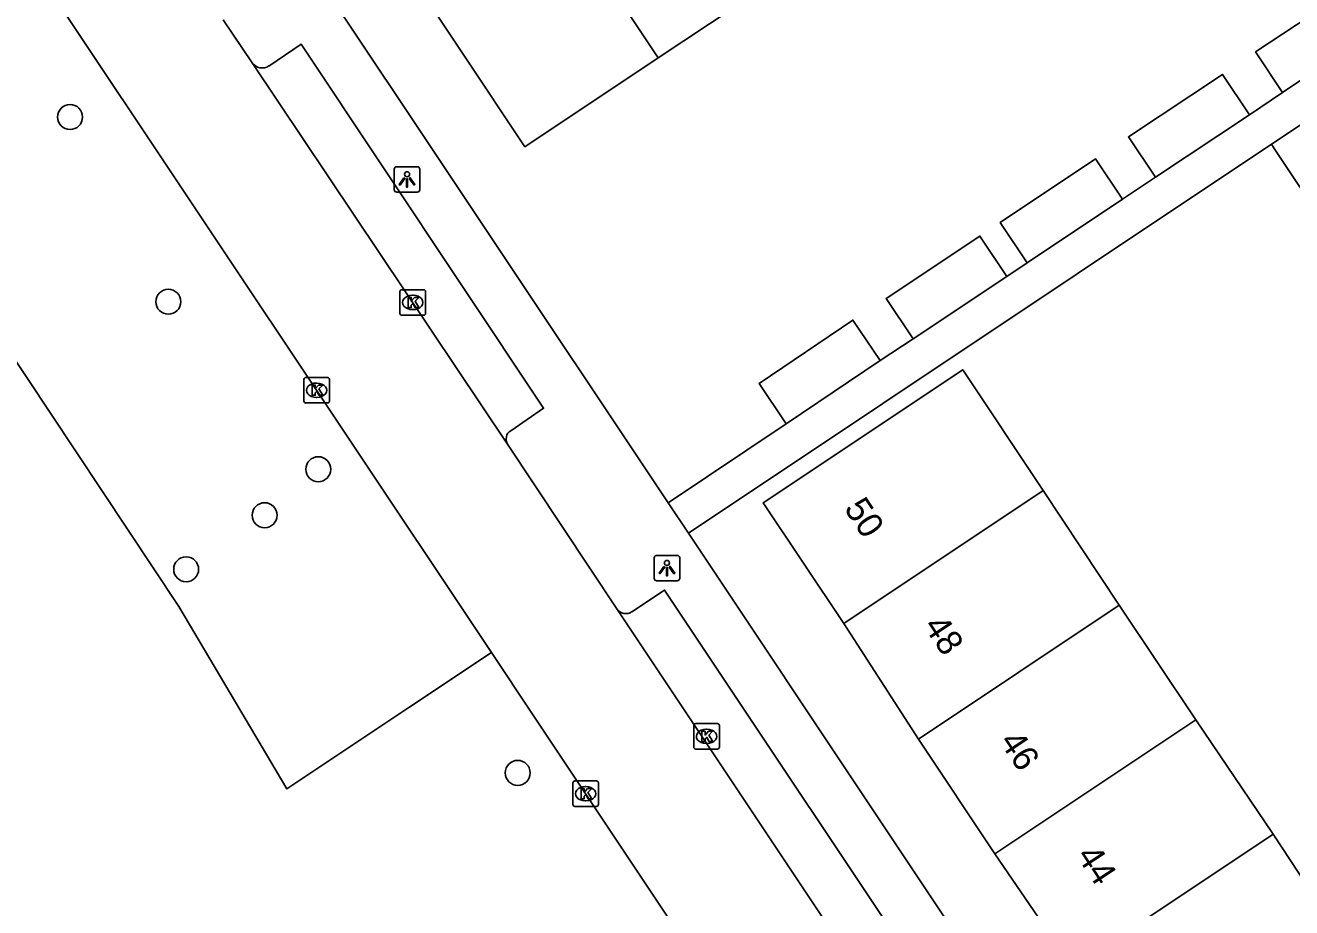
# Model space of a CAD drawing. Extents: x 158352 to 159489, y 383828 to 384597.
# Drawn here: x 158635.92 to 158685.53, y 384292.05 to 384326.59 of the extents above; entities that cross this region are included whole.
import ezdxf

# ---------------------------------------------------------------- set-up
doc = ezdxf.new("R2010")
doc.units = 0
for name, color, linetype in [('IMGEO_Boom', 7, 'Continuous'), ('IMGEO_Groenvoorziening', 7, 'Continuous'), ('IMGEO_Kolk', 7, 'Continuous'), ('IMGEO_Lichtpunt', 7, 'Continuous'), ('IMGEO_Pand', 7, 'Continuous'), ('IMGEO_Pand_nummerreeks', 7, 'Continuous'), ('IMGEO_Rijbaan_lokaal_open', 7, 'Continuous'), ('IMGEO_Voetpad_open', 7, 'Continuous')]:
    doc.layers.add(name, color=color, linetype=linetype)

msp = doc.modelspace()

# ---------------------------------------------------------------- linework, layer by layer
at = {"layer": 'IMGEO_Boom'}
for centre in [(158637.667, 384322.998), (158641.518, 384315.767), (158647.39, 384309.211), (158645.288, 384307.409), (158642.216, 384305.295), (158655.205, 384297.324)]:
    msp.add_circle(centre, 0.489, dxfattribs=at)
at = {"layer": 'IMGEO_Groenvoorziening'}
msp.add_lwpolyline([(158636.795, 384328.082), (158633.416, 384326.021), (158630.193, 384330.83), (158625.907, 384327.948), (158641.933, 384303.831), (158646.165, 384296.695), (158646.519, 384296.93), (158650.939, 384299.878), (158654.177, 384302.038)], dxfattribs=at)
at = {"layer": 'IMGEO_Kolk'}
for p, q in [((158650.592, 384315.312), (158650.592, 384316.164)), ((158650.667, 384316.238), (158651.519, 384316.238)), ((158651.08, 384316.018), (158651.105, 384316.018)), ((158651.593, 384316.164), (158651.593, 384315.312)), ((158651.103, 384315.458), (158651.078, 384315.458)), ((158651.519, 384315.238), (158650.667, 384315.238)), ((158646.827, 384311.877), (158646.827, 384312.729)), ((158646.902, 384312.803), (158647.754, 384312.803)), ((158647.315, 384312.583), (158647.34, 384312.583)), ((158647.828, 384312.729), (158647.828, 384311.877)), ((158647.338, 384312.023), (158647.313, 384312.023)), ((158647.754, 384311.803), (158646.902, 384311.803)), ((158662.103, 384298.329), (158662.103, 384299.181)), ((158662.178, 384299.255), (158663.03, 384299.255)), ((158662.591, 384299.035), (158662.616, 384299.035)), ((158663.104, 384299.181), (158663.104, 384298.329)), ((158662.614, 384298.475), (158662.589, 384298.475)), ((158663.03, 384298.255), (158662.178, 384298.255)), ((158657.441, 384297.008), (158658.293, 384297.008)), ((158657.366, 384296.082), (158657.366, 384296.934)), ((158657.854, 384296.788), (158657.879, 384296.788)), ((158658.367, 384296.934), (158658.367, 384296.082)), ((158658.293, 384296.008), (158657.441, 384296.008)), ((158657.877, 384296.228), (158657.852, 384296.228))]:
    msp.add_line(p, q, dxfattribs=at)
for points in [[(158650.592, 384315.312), (158650.592, 384316.164)], [(158650.667, 384316.238), (158651.519, 384316.238)], [(158650.913, 384315.938), (158651.036, 384315.938), (158651.036, 384315.787), (158651.166, 384315.938), (158651.33, 384315.938), (158651.184, 384315.787), (158651.337, 384315.538), (158651.185, 384315.538), (158651.1, 384315.702), (158651.036, 384315.635), (158651.036, 384315.538), (158650.913, 384315.538), (158650.913, 384315.938)], [(158651.593, 384316.164), (158651.593, 384315.312)], [(158651.519, 384315.238), (158650.667, 384315.238)], [(158646.827, 384311.877), (158646.827, 384312.729)], [(158646.902, 384312.803), (158647.754, 384312.803)], [(158647.148, 384312.503), (158647.271, 384312.503), (158647.271, 384312.352), (158647.401, 384312.503), (158647.565, 384312.503), (158647.419, 384312.352), (158647.572, 384312.103), (158647.42, 384312.103), (158647.335, 384312.267), (158647.271, 384312.2), (158647.271, 384312.103), (158647.148, 384312.103), (158647.148, 384312.503)], [(158647.828, 384312.729), (158647.828, 384311.877)], [(158647.754, 384311.803), (158646.902, 384311.803)], [(158662.103, 384298.329), (158662.103, 384299.181)], [(158662.178, 384299.255), (158663.03, 384299.255)], [(158662.424, 384298.955), (158662.547, 384298.955), (158662.547, 384298.804), (158662.677, 384298.955), (158662.841, 384298.955), (158662.695, 384298.804), (158662.848, 384298.555), (158662.696, 384298.555), (158662.611, 384298.719), (158662.547, 384298.652), (158662.547, 384298.555), (158662.424, 384298.555), (158662.424, 384298.955)], [(158663.104, 384299.181), (158663.104, 384298.329)], [(158663.03, 384298.255), (158662.178, 384298.255)], [(158657.441, 384297.008), (158658.293, 384297.008)], [(158657.366, 384296.082), (158657.366, 384296.934)], [(158657.687, 384296.708), (158657.81, 384296.708), (158657.81, 384296.557), (158657.94, 384296.708), (158658.104, 384296.708), (158657.958, 384296.557), (158658.111, 384296.308), (158657.959, 384296.308), (158657.874, 384296.472), (158657.81, 384296.405), (158657.81, 384296.308), (158657.687, 384296.308), (158657.687, 384296.708)], [(158658.367, 384296.934), (158658.367, 384296.082)], [(158658.293, 384296.008), (158657.441, 384296.008)]]:
    msp.add_lwpolyline(points, dxfattribs=at)
for centre, start, end in [((158650.669, 384316.162), 91.552, 178.448), ((158650.669, 384316.162), 91.552, 178.448), ((158651.517, 384316.162), 1.552, 88.448), ((158651.517, 384316.162), 1.552, 88.448), ((158650.669, 384315.314), 181.552, 268.448), ((158650.669, 384315.314), 181.552, 268.448), ((158651.517, 384315.314), 271.552, 358.448), ((158651.517, 384315.314), 271.552, 358.448), ((158646.904, 384312.727), 91.552, 178.448), ((158646.904, 384312.727), 91.552, 178.448), ((158647.752, 384312.727), 1.552, 88.448), ((158647.752, 384312.727), 1.552, 88.448), ((158646.904, 384311.879), 181.552, 268.448), ((158646.904, 384311.879), 181.552, 268.448), ((158647.752, 384311.879), 271.552, 358.448), ((158647.752, 384311.879), 271.552, 358.448), ((158662.18, 384299.179), 91.552, 178.448), ((158662.18, 384299.179), 91.552, 178.448), ((158663.028, 384299.179), 1.552, 88.448), ((158663.028, 384299.179), 1.552, 88.448), ((158662.18, 384298.331), 181.552, 268.448), ((158662.18, 384298.331), 181.552, 268.448), ((158663.028, 384298.331), 271.552, 358.448), ((158663.028, 384298.331), 271.552, 358.448), ((158657.443, 384296.932), 91.552, 178.448), ((158657.443, 384296.932), 91.552, 178.448), ((158658.291, 384296.932), 1.552, 88.448), ((158658.291, 384296.932), 1.552, 88.448), ((158657.443, 384296.084), 181.552, 268.448), ((158657.443, 384296.084), 181.552, 268.448), ((158658.291, 384296.084), 271.552, 358.448), ((158658.291, 384296.084), 271.552, 358.448)]:
    msp.add_arc(centre, 0.0765, start, end, dxfattribs=at)
for centre, major_axis, ratio, start_param, end_param in [((158651.079, 384315.738), (-0.387, 0.002), 0.722429, 4.712389, 7.853982), ((158651.104, 384315.738), (-0.39, 0.002), 0.717154, 1.570796, 4.712389), ((158647.314, 384312.303), (-0.387, 0.002), 0.722429, 4.712389, 7.853982), ((158647.339, 384312.303), (-0.39, 0.002), 0.717154, 1.570796, 4.712389), ((158662.59, 384298.755), (-0.387, 0.002), 0.722429, 4.712389, 7.853982), ((158662.615, 384298.755), (-0.39, 0.002), 0.717154, 1.570796, 4.712389), ((158657.853, 384296.508), (-0.387, 0.002), 0.722429, 4.712389, 7.853982), ((158657.878, 384296.508), (-0.39, 0.002), 0.717154, 1.570796, 4.712389)]:
    msp.add_ellipse(centre, major_axis=major_axis, ratio=ratio, start_param=start_param, end_param=end_param, dxfattribs=at)
at = {"layer": 'IMGEO_Lichtpunt'}
for p, q in [((158650.37, 384320.959), (158650.37, 384320.152)), ((158650.37, 384320.959), (158650.37, 384320.152)), ((158651.272, 384321.054), (158650.464, 384321.054)), ((158651.272, 384321.054), (158650.464, 384321.054)), ((158651.366, 384320.152), (158651.366, 384320.959)), ((158651.366, 384320.152), (158651.366, 384320.959)), ((158650.464, 384320.058), (158651.272, 384320.058)), ((158650.464, 384320.058), (158651.272, 384320.058)), ((158660.554, 384305.744), (158660.554, 384304.937)), ((158660.554, 384305.744), (158660.554, 384304.937)), ((158661.456, 384305.839), (158660.648, 384305.839)), ((158661.456, 384305.839), (158660.648, 384305.839)), ((158661.55, 384304.937), (158661.55, 384305.744)), ((158661.55, 384304.937), (158661.55, 384305.744)), ((158660.648, 384304.843), (158661.456, 384304.843)), ((158660.648, 384304.843), (158661.456, 384304.843))]:
    msp.add_line(p, q, dxfattribs=at)
for points in [[(158650.744, 384320.623), (158650.783, 384320.595), (158650.595, 384320.333), (158650.557, 384320.36), (158650.744, 384320.623)], [(158650.846, 384320.575), (158650.893, 384320.575), (158650.893, 384320.253), (158650.846, 384320.253), (158650.846, 384320.575)], [(158650.956, 384320.595), (158650.994, 384320.622), (158651.181, 384320.36), (158651.142, 384320.332), (158650.956, 384320.595)], [(158660.928, 384305.408), (158660.967, 384305.38), (158660.779, 384305.118), (158660.741, 384305.145), (158660.928, 384305.408)], [(158661.14, 384305.38), (158661.178, 384305.407), (158661.365, 384305.145), (158661.326, 384305.117), (158661.14, 384305.38)], [(158661.03, 384305.36), (158661.077, 384305.36), (158661.077, 384305.038), (158661.03, 384305.038), (158661.03, 384305.36)]]:
    msp.add_lwpolyline(points, dxfattribs=at)
for centre in [(158650.869, 384320.757), (158661.053, 384305.542)]:
    msp.add_circle(centre, 0.0994, dxfattribs=at)
for centre, start, end in [((158650.464, 384320.959), 90, 180), ((158650.464, 384320.959), 90, 180), ((158651.272, 384320.959), 0, 90), ((158651.272, 384320.959), 0, 90), ((158650.464, 384320.152), 180, 270), ((158650.464, 384320.152), 180, 270), ((158651.272, 384320.152), 270, 0), ((158651.272, 384320.152), 270, 360), ((158660.648, 384305.744), 90, 180), ((158660.648, 384305.744), 90, 180), ((158661.456, 384305.744), 0, 90), ((158661.456, 384305.744), 0, 90), ((158660.648, 384304.937), 180, 270), ((158660.648, 384304.937), 180, 270), ((158661.456, 384304.937), 270, 0), ((158661.456, 384304.937), 270, 360)]:
    msp.add_arc(centre, 0.0946, start, end, dxfattribs=at)
at = {"layer": 'IMGEO_Pand'}
for points in [[(158660.712, 384325.314), (158655.487, 384321.833), (158650.601, 384329.173), (158655.799, 384332.679)], [(158655.799, 384332.679), (158660.712, 384325.314)], [(158665.697, 384328.629), (158660.712, 384325.314)], [(158685.166, 384323.963), (158684.114, 384325.544), (158687.812, 384328.006), (158688.865, 384326.424)], [(158688.865, 384326.424), (158685.166, 384323.963)], [(158680.185, 384320.637), (158679.133, 384322.219), (158682.821, 384324.669), (158683.873, 384323.087)], [(158683.873, 384323.087), (158680.185, 384320.637)], [(158684.731, 384321.934), (158686.327, 384322.997), (158688.413, 384319.835)], [(158688.413, 384319.835), (158686.834, 384318.782), (158684.84, 384321.77), (158684.731, 384321.934)], [(158675.159, 384317.285), (158674.106, 384318.866), (158677.844, 384321.359), (158678.895, 384319.777)], [(158678.895, 384319.777), (158675.159, 384317.285)], [(158670.698, 384314.313), (158669.645, 384315.894), (158673.315, 384318.339), (158674.369, 384316.758)], [(158674.369, 384316.758), (158670.698, 384314.313)], [(158665.725, 384310.981), (158664.658, 384312.562), (158668.339, 384315.047), (158669.406, 384313.466)], [(158669.406, 384313.466), (158665.725, 384310.981)], [(158667.975, 384303.17), (158664.824, 384307.897), (158672.637, 384313.107), (158675.785, 384308.374)], [(158675.785, 384308.374), (158667.975, 384303.17)], [(158678.774, 384303.893), (158675.785, 384308.374)], [(158670.901, 384298.647), (158678.774, 384303.893)], [(158678.774, 384303.893), (158681.773, 384299.397)], [(158667.975, 384303.17), (158670.901, 384298.647)], [(158681.773, 384299.397), (158673.9, 384294.152)], [(158684.797, 384294.918), (158681.773, 384299.397)], [(158673.9, 384294.152), (158670.901, 384298.647)], [(158684.797, 384294.918), (158676.958, 384289.696)], [(158687.761, 384290.42), (158684.797, 384294.918)], [(158673.9, 384294.152), (158676.958, 384289.696)]]:
    msp.add_lwpolyline(points, dxfattribs=at)
at = {"layer": 'IMGEO_Rijbaan_lokaal_open'}
for points in [[(158636.795, 384328.082), (158654.177, 384302.038)], [(158644.803, 384325.125), (158643.662, 384326.8)], [(158654.809, 384310.191), (158644.803, 384325.125)], [(158659.086, 384303.74), (158654.809, 384310.191)], [(158693.594, 384252.04), (158659.086, 384303.74)], [(158654.177, 384302.038), (158655.789, 384299.623), (158691.316, 384246.356)]]:
    msp.add_lwpolyline(points, dxfattribs=at)
at = {"layer": 'IMGEO_Voetpad_open'}
for points in [[(158646.346, 384330.011), (158661.096, 384307.894)], [(158654.934, 384310.716), (158656.217, 384311.6), (158646.725, 384325.848), (158645.456, 384324.995)], [(158683.873, 384323.087), (158685.166, 384323.963)], [(158661.89, 384306.702), (158684.731, 384321.934)], [(158678.895, 384319.777), (158680.185, 384320.637)], [(158674.369, 384316.758), (158675.159, 384317.285)], [(158669.406, 384313.466), (158670.698, 384314.313)], [(158661.096, 384307.894), (158665.725, 384310.981)], [(158661.096, 384307.894), (158661.89, 384306.702)], [(158661.89, 384306.702), (158737.694, 384193.032)], [(158693.763, 384252.543), (158695.03, 384253.434), (158660.956, 384304.482), (158659.679, 384303.634)]]:
    msp.add_lwpolyline(points, dxfattribs=at)
for centre, radius, start, end in [((158645.197, 384325.401), 0.481, 214.9925, 302.4889), ((158655.125, 384310.393), 0.375, 120.5836, 212.6314), ((158659.435, 384303.983), 0.425, 214.7746, 304.956)]:
    msp.add_arc(centre, radius, start, end, dxfattribs=at)

# ---------------------------------------------------------------- texts
at = {"layer": 'IMGEO_Pand_nummerreeks'}
for s, rotation, p in [('50', 303.2503, (158667.967, 384307.676)), ('48', 303.6816, (158671.079, 384303.075)), ('46', 303.5276, (158674.052, 384298.553)), ('44', 303.2387, (158677.071, 384294.081))]:
    msp.add_text(s, height=1, rotation=rotation, dxfattribs=at).set_placement(p)

doc.saveas('drawing.dxf')
